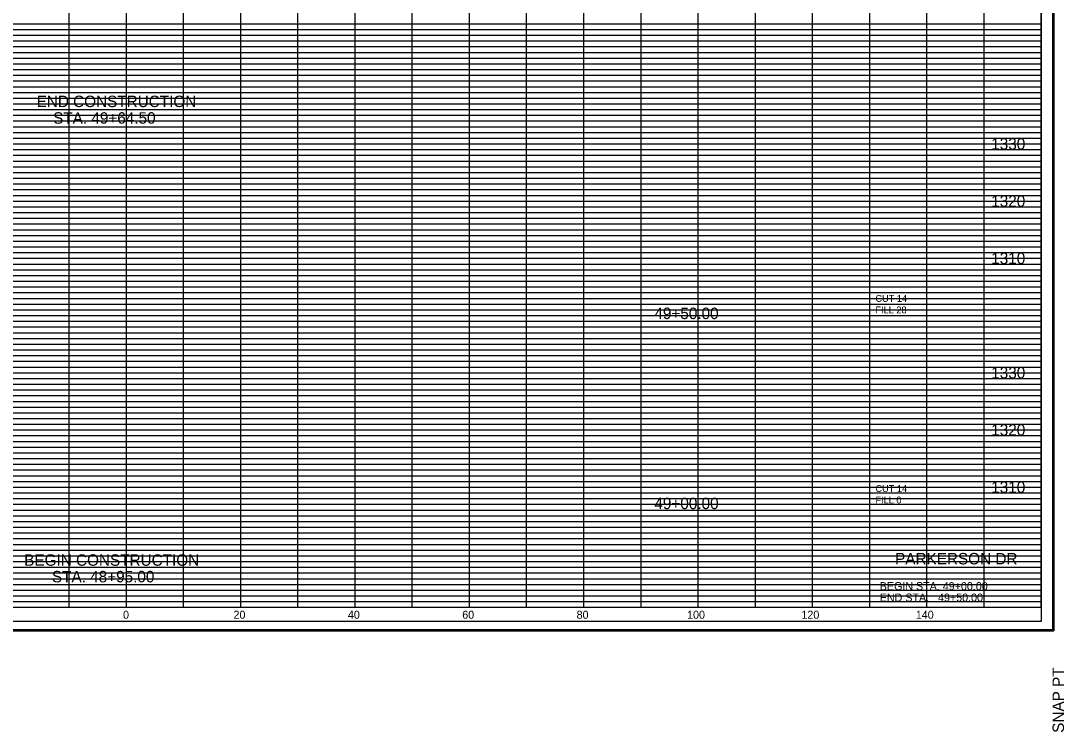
# Model space of a CAD drawing. Extents: x 980 to 1324, y 978 to 1227.
# Drawn here: x 1141.5 to 1324, y 978.2 to 1102.5 of the extents above; entities that cross this region are included whole.
import ezdxf

# ---------------------------------------------------------------- set-up
doc = ezdxf.new("R2010")
doc.units = 0
for name, color, linetype in [('DESIGN - SHEET - Corner Text', 7, 'Continuous'), ('DESIGN - SHEET - Light Grid', 7, 'Continuous'), ('DESIGN - SHEET - Linework', 7, 'Continuous'), ('DESIGN - SHEET - Plot Shape', 7, 'Continuous'), ('DESIGN - TYPICAL - Finished Grade and Subgrade', 7, 'Continuous'), ('DESIGN - TYPICAL - Text', 7, 'Continuous')]:
    doc.layers.add(name, color=color, linetype=linetype)

# ---------------------------------------------------------------- blocks, each defined once
blk = doc.blocks.new('XSTSHT')
at = {"layer": 'DESIGN - SHEET - Light Grid'}
for p, q in [((8, 10.2), (16, 10.2)), ((8, 10.1), (16, 10.1)), ((16, 10.2), (24, 10.2)), ((16, 10.1), (24, 10.1)), ((24, 10.2), (32, 10.2)), ((24, 10.1), (32, 10.1)), ((8, 9.9), (16, 9.9)), ((16, 9.9), (24, 9.9)), ((24, 9.9), (32, 9.9)), ((8, 9.8), (16, 9.8)), ((8, 9.7), (16, 9.7)), ((16, 9.8), (24, 9.8)), ((16, 9.7), (24, 9.7)), ((24, 9.8), (32, 9.8)), ((24, 9.7), (32, 9.7)), ((8, 9.6), (16, 9.6)), ((8, 9.5), (16, 9.5)), ((16, 9.6), (24, 9.6)), ((16, 9.5), (24, 9.5)), ((24, 9.6), (32, 9.6)), ((24, 9.5), (32, 9.5)), ((8, 9.4), (16, 9.4)), ((16, 9.4), (24, 9.4)), ((24, 9.4), (32, 9.4)), ((8, 9.3), (16, 9.3)), ((8, 9.2), (16, 9.2)), ((16, 9.3), (24, 9.3)), ((16, 9.2), (24, 9.2)), ((24, 9.3), (32, 9.3)), ((24, 9.2), (32, 9.2)), ((8, 9.1), (16, 9.1)), ((16, 9.1), (24, 9.1)), ((24, 9.1), (32, 9.1)), ((8, 8.9), (16, 8.9)), ((8, 8.8), (16, 8.8)), ((16, 8.9), (24, 8.9)), ((16, 8.8), (24, 8.8)), ((24, 8.9), (32, 8.9)), ((24, 8.8), (32, 8.8)), ((8, 8.7), (16, 8.7)), ((8, 8.6), (16, 8.6)), ((16, 8.7), (24, 8.7)), ((16, 8.6), (24, 8.6)), ((24, 8.7), (32, 8.7)), ((24, 8.6), (32, 8.6)), ((8, 8.5), (16, 8.5)), ((8, 8.4), (16, 8.4)), ((16, 8.5), (24, 8.5)), ((16, 8.4), (24, 8.4)), ((24, 8.5), (32, 8.5)), ((24, 8.4), (32, 8.4)), ((8, 8.3), (16, 8.3)), ((16, 8.3), (24, 8.3)), ((24, 8.3), (32, 8.3)), ((8, 8.2), (16, 8.2)), ((8, 8.1), (16, 8.1)), ((16, 8.2), (24, 8.2)), ((16, 8.1), (24, 8.1)), ((24, 8.2), (32, 8.2)), ((24, 8.1), (32, 8.1)), ((8, 7.9), (16, 7.9)), ((16, 7.9), (24, 7.9)), ((24, 7.9), (32, 7.9)), ((8, 7.8), (16, 7.8)), ((8, 7.7), (16, 7.7)), ((16, 7.8), (24, 7.8)), ((16, 7.7), (24, 7.7)), ((24, 7.8), (32, 7.8)), ((24, 7.7), (32, 7.7)), ((8, 7.6), (16, 7.6)), ((8, 7.5), (16, 7.5)), ((16, 7.6), (24, 7.6)), ((16, 7.5), (24, 7.5)), ((24, 7.6), (32, 7.6)), ((24, 7.5), (32, 7.5)), ((8, 7.4), (16, 7.4)), ((8, 7.3), (16, 7.3)), ((16, 7.4), (24, 7.4)), ((16, 7.3), (24, 7.3)), ((24, 7.4), (32, 7.4)), ((24, 7.3), (32, 7.3)), ((8, 7.2), (16, 7.2)), ((16, 7.2), (24, 7.2)), ((24, 7.2), (32, 7.2)), ((8, 7.1), (16, 7.1)), ((16, 7.1), (24, 7.1)), ((24, 7.1), (32, 7.1)), ((8, 6.9), (16, 6.9)), ((8, 6.8), (16, 6.8)), ((16, 6.9), (24, 6.9)), ((16, 6.8), (24, 6.8)), ((24, 6.9), (32, 6.9)), ((24, 6.8), (32, 6.8)), ((8, 6.7), (16, 6.7)), ((8, 6.6), (16, 6.6)), ((16, 6.7), (24, 6.7)), ((16, 6.6), (24, 6.6)), ((24, 6.7), (32, 6.7)), ((24, 6.6), (32, 6.6)), ((8, 6.5), (16, 6.5)), ((8, 6.4), (16, 6.4)), ((16, 6.5), (24, 6.5)), ((16, 6.4), (24, 6.4)), ((24, 6.5), (32, 6.5)), ((24, 6.4), (32, 6.4)), ((8, 6.3), (16, 6.3)), ((16, 6.3), (24, 6.3)), ((24, 6.3), (32, 6.3)), ((8, 6.2), (16, 6.2)), ((8, 6.1), (16, 6.1)), ((16, 6.2), (24, 6.2)), ((16, 6.1), (24, 6.1)), ((24, 6.2), (32, 6.2)), ((24, 6.1), (32, 6.1)), ((8, 5.9), (16, 5.9)), ((16, 5.9), (24, 5.9)), ((24, 5.9), (32, 5.9)), ((8, 5.8), (16, 5.8)), ((8, 5.7), (16, 5.7)), ((16, 5.8), (24, 5.8)), ((16, 5.7), (24, 5.7)), ((24, 5.8), (32, 5.8)), ((24, 5.7), (32, 5.7)), ((8, 5.6), (16, 5.6)), ((8, 5.5), (16, 5.5)), ((16, 5.6), (24, 5.6)), ((16, 5.5), (24, 5.5)), ((24, 5.6), (32, 5.6)), ((24, 5.5), (32, 5.5)), ((8, 5.4), (16, 5.4)), ((8, 5.3), (16, 5.3)), ((16, 5.4), (24, 5.4)), ((16, 5.3), (24, 5.3)), ((24, 5.4), (32, 5.4)), ((24, 5.3), (32, 5.3)), ((8, 5.2), (16, 5.2)), ((16, 5.2), (24, 5.2)), ((24, 5.2), (32, 5.2)), ((8, 5.1), (16, 5.1)), ((16, 5.1), (24, 5.1)), ((24, 5.1), (32, 5.1)), ((8, 4.9), (16, 4.9)), ((8, 4.8), (16, 4.8)), ((16, 4.9), (24, 4.9)), ((16, 4.8), (24, 4.8)), ((24, 4.9), (32, 4.9)), ((24, 4.8), (32, 4.8)), ((8, 4.7), (16, 4.7)), ((8, 4.6), (16, 4.6)), ((16, 4.7), (24, 4.7)), ((16, 4.6), (24, 4.6)), ((24, 4.7), (32, 4.7)), ((24, 4.6), (32, 4.6)), ((8, 4.5), (16, 4.5)), ((8, 4.4), (16, 4.4)), ((16, 4.5), (24, 4.5)), ((16, 4.4), (24, 4.4)), ((24, 4.5), (32, 4.5)), ((24, 4.4), (32, 4.4)), ((8, 4.3), (16, 4.3)), ((8, 4.2), (16, 4.2)), ((16, 4.3), (24, 4.3)), ((16, 4.2), (24, 4.2)), ((24, 4.3), (32, 4.3)), ((24, 4.2), (32, 4.2)), ((8, 4.1), (16, 4.1)), ((16, 4.1), (24, 4.1)), ((24, 4.1), (32, 4.1)), ((8, 3.9), (16, 3.9)), ((16, 3.9), (24, 3.9)), ((24, 3.9), (32, 3.9)), ((8, 3.8), (16, 3.8)), ((8, 3.7), (16, 3.7)), ((16, 3.8), (24, 3.8)), ((16, 3.7), (24, 3.7)), ((24, 3.8), (32, 3.8)), ((24, 3.7), (32, 3.7)), ((8, 3.6), (16, 3.6)), ((8, 3.5), (16, 3.5)), ((16, 3.6), (24, 3.6)), ((16, 3.5), (24, 3.5)), ((24, 3.6), (32, 3.6)), ((24, 3.5), (32, 3.5)), ((8, 3.4), (16, 3.4)), ((8, 3.3), (16, 3.3)), ((16, 3.4), (24, 3.4)), ((16, 3.3), (24, 3.3)), ((24, 3.4), (32, 3.4)), ((24, 3.3), (32, 3.3)), ((8, 3.2), (16, 3.2)), ((16, 3.2), (24, 3.2)), ((24, 3.2), (32, 3.2)), ((8, 3.1), (16, 3.1)), ((16, 3.1), (24, 3.1)), ((24, 3.1), (32, 3.1)), ((8, 2.9), (16, 2.9)), ((8, 2.8), (16, 2.8)), ((16, 2.9), (24, 2.9)), ((16, 2.8), (24, 2.8)), ((24, 2.9), (32, 2.9)), ((24, 2.8), (32, 2.8)), ((8, 2.7), (16, 2.7)), ((8, 2.6), (16, 2.6)), ((16, 2.7), (24, 2.7)), ((16, 2.6), (24, 2.6)), ((24, 2.7), (32, 2.7)), ((24, 2.6), (32, 2.6)), ((8, 2.5), (16, 2.5)), ((8, 2.4), (16, 2.4)), ((16, 2.5), (24, 2.5)), ((16, 2.4), (24, 2.4)), ((24, 2.5), (32, 2.5)), ((24, 2.4), (32, 2.4)), ((8, 2.3), (16, 2.3)), ((8, 2.2), (16, 2.2)), ((16, 2.3), (24, 2.3)), ((16, 2.2), (24, 2.2)), ((24, 2.3), (32, 2.3)), ((24, 2.2), (32, 2.2)), ((8, 2.1), (16, 2.1)), ((16, 2.1), (24, 2.1)), ((24, 2.1), (32, 2.1)), ((8, 1.9), (16, 1.9)), ((16, 1.9), (24, 1.9)), ((24, 1.9), (32, 1.9)), ((8, 1.8), (16, 1.8)), ((8, 1.7), (16, 1.7)), ((16, 1.8), (24, 1.8)), ((16, 1.7), (24, 1.7)), ((24, 1.8), (32, 1.8)), ((24, 1.7), (32, 1.7)), ((8, 1.6), (16, 1.6)), ((8, 1.5), (16, 1.5)), ((16, 1.6), (24, 1.6)), ((16, 1.5), (24, 1.5)), ((24, 1.6), (32, 1.6)), ((24, 1.5), (32, 1.5)), ((8, 1.4), (16, 1.4)), ((8, 1.3), (16, 1.3)), ((16, 1.4), (24, 1.4)), ((16, 1.3), (24, 1.3)), ((24, 1.4), (32, 1.4)), ((24, 1.3), (32, 1.3)), ((8, 1.2), (16, 1.2)), ((8, 1.1), (16, 1.1)), ((16, 1.2), (24, 1.2)), ((16, 1.1), (24, 1.1)), ((24, 1.2), (32, 1.2)), ((24, 1.1), (32, 1.1)), ((8, 0.9), (16, 0.9)), ((8, 0.8), (16, 0.8)), ((16, 0.9), (24, 0.9)), ((16, 0.8), (24, 0.8)), ((24, 0.9), (32, 0.9)), ((24, 0.8), (32, 0.8)), ((8, 0.7), (16, 0.7)), ((8, 0.6), (16, 0.6)), ((16, 0.7), (24, 0.7)), ((16, 0.6), (24, 0.6)), ((24, 0.7), (32, 0.7)), ((24, 0.6), (32, 0.6)), ((8, 0.5), (16, 0.5)), ((8, 0.4), (16, 0.4)), ((16, 0.5), (24, 0.5)), ((16, 0.4), (24, 0.4)), ((24, 0.5), (32, 0.5)), ((24, 0.4), (32, 0.4)), ((8, 0.3), (16, 0.3)), ((8, 0.2), (16, 0.2)), ((16, 0.3), (24, 0.3)), ((16, 0.2), (24, 0.2)), ((24, 0.3), (32, 0.3)), ((24, 0.2), (32, 0.2)), ((8, 0.1), (16, 0.1)), ((16, 0.1), (24, 0.1)), ((24, 0.1), (32, 0.1))]:
    blk.add_line(p, q, dxfattribs=at)
at = {"layer": 'DESIGN - SHEET - Linework'}
for p, q in [((32.217, 21.414), (32.217, -0.414)), ((15, 0), (15, 21)), ((16, 0), (16, 21)), ((17, 0), (17, 21)), ((18, 0), (18, 21)), ((19, 0), (19, 21)), ((20, 0), (20, 21)), ((21, 0), (21, 21)), ((22, 0), (22, 21)), ((23, 0), (23, 21)), ((24, 0), (24, 21)), ((25, 0), (25, 21)), ((26, 0), (26, 21)), ((27, 0), (27, 21)), ((28, 0), (28, 20)), ((29, 0), (29, 20)), ((30, 0), (30, 20)), ((31, 0), (31, 20)), ((0, 10), (32, 10)), ((0, 9), (32, 9)), ((0, 8), (32, 8)), ((0, 7), (32, 7)), ((0, 6), (32, 6)), ((0, 5), (32, 5)), ((0, 4), (32, 4)), ((0, 3), (32, 3)), ((0, 2), (32, 2)), ((0, 1), (32, 1)), ((-1.823, -0.414), (32.217, -0.414))]:
    blk.add_line(p, q, dxfattribs=at)
blk.add_lwpolyline([(0, 21), (0, 0), (32, 0), (32, 21), (0, 21)], dxfattribs=at)
at = {"layer": 'DESIGN - SHEET - Plot Shape'}
for points in [[(-1.803, 21.394), (32.197, 21.394), (32.197, -0.394), (-1.803, -0.394)], [(-0.85, 21), (32, 21), (32, -0.25), (-0.85, -0.25)]]:
    blk.add_lwpolyline(points, close=True, dxfattribs=at)
at = {"layer": 'DESIGN - SHEET - Corner Text'}
blk.add_text('SNAP PT  ', height=0.2, rotation=90, dxfattribs=at).set_placement((32.397, -2.194))

msp = doc.modelspace()

# ---------------------------------------------------------------- block references
at = {"layer": 'DESIGN - TYPICAL - Finished Grade and Subgrade', "xscale": 10, "yscale": 10}
msp.add_blockref('XSTSHT', (1000, 1000), dxfattribs=at)

# ---------------------------------------------------------------- texts
at = {"layer": 'DESIGN - SHEET - Corner Text'}
for s, height, p in [('1330', 2, (1311.25, 1080)), ('1320', 2, (1311.25, 1070)), ('1310', 2, (1311.25, 1060)), ('49+50.00', 2, (1252.34, 1050.38)), ('1330', 2, (1311.25, 1040)), ('1320', 2, (1311.25, 1030)), ('1310', 2, (1311.25, 1020)), ('49+00.00', 2, (1252.34, 1017.16)), ('PARKERSON DR', 2, (1294.44, 1007.5)), ('BEGIN STA. 49+00.00', 1.4, (1291.75, 1003)), ('END STA.   49+50.00', 1.4, (1291.75, 1001)), ('0', 1.4, (1159.42, 998)), ('0', 1.4, (1159.42, 998)), ('20', 1.4, (1178.74, 998)), ('40', 1.4, (1198.74, 998)), ('60', 1.4, (1218.74, 998)), ('80', 1.4, (1238.74, 998)), ('100', 1.4, (1258.06, 998)), ('120', 1.4, (1278.06, 998)), ('140', 1.4, (1298.06, 998))]:
    msp.add_text(s, height=height, dxfattribs=at).set_placement(p)
at = {"layer": 'DESIGN - TYPICAL - Text'}
for s, height, p in [('END CONSTRUCTION', 2, (1144.3, 1087.43)), ('STA. 49+64.50', 2, (1147.19, 1084.53)), ('CUT 14', 1.2, (1291, 1053.38)), ('FILL 28', 1.2, (1291, 1051.38)), ('CUT 14', 1.2, (1291, 1020.16)), ('FILL 0', 1.2, (1291, 1018.16)), ('BEGIN CONSTRUCTION', 2, (1142.13, 1007.26)), ('STA. 48+95.00', 2, (1146.98, 1004.36))]:
    msp.add_text(s, height=height, dxfattribs=at).set_placement(p)

doc.saveas('drawing.dxf')
